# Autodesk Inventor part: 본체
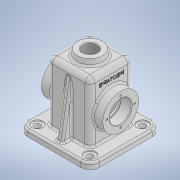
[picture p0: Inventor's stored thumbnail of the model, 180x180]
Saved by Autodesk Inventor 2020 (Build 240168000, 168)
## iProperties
Created: 2021-07
Part Number: 본체
Material: 일반
Document SubType Name: Modeling
Designer: Owner
Density: 1 g/cm^3
Appearance: 기본값
Author: Owner
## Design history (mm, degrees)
sketch "스케치1"
  geometry: L1 (34, 34)-(-34, 34); L2 (-34, 34)-(-34, -34); L3 (-34, -34)-(34, -34); L4 (34, -34)-(34, 34); L5 (34, 34)-(-34, -34); L6 (-34, 34)-(34, -34); 1 further point
  constraints: 12 end point, 2 midpoint, 2 parallel, 1 horizontal, 1 perpendicular
  dimensions: "d0" = 68 distance of L3.end L2.end; "d1" = 68 distance of L2.end L1.end
extrude "돌출1" new body sketch "스케치1" distance "d2" = 105; taper "d3" = 0 deg
fillet "모깎기1" dims "d4" = 8
feature "쉘1" dims "d5" = 5
sketch "스케치2"
  geometry: L1 (-57, 57)-(57, 57); L2 (57, 57)-(57, -57); L3 (57, -57)-(-57, -57); L4 (-57, -57)-(-57, 57); L5 (-57, 57)-(57, -57); L6 (57, 57)-(-57, -57); L7 (-26, 29)-(26, 29) reference; L8 (29, 26)-(29, -26) reference; L9 (26, -29)-(-26, -29) reference; L10 (-29, -26)-(-29, 26) reference; L11 (34, 26)-(34, -26) reference; L12 (-26, 34)-(26, 34) reference; L13 (-34, -26)-(-34, 26) reference; L14 (26, -34)-(-26, -34) reference; A1 r 3 centre (-26, 26) between (-26, 29) and (-29, 26) reference; A2 r 3 centre (26, 26) between (29, 26) and (26, 29) reference; A3 r 3 centre (26, -26) between (26, -29) and (29, -26) reference; A4 r 3 centre (-26, -26) between (-29, -26) and (-26, -29) reference; A5 r 8 centre (26, -26) between (26, -34) and (34, -26) reference; A6 r 8 centre (26, 26) between (34, 26) and (26, 34) reference; A7 r 8 centre (-26, 26) between (-26, 34) and (-34, 26) reference; A8 r 8 centre (-26, -26) between (-34, -26) and (-26, -34) reference; 1 further point
  constraints: 12 end point, 2 midpoint, 2 parallel, 1 horizontal, 1 perpendicular
  dimensions: "d6" = 114 distance of L2.end L3.end; "d7" = 114 distance of L1.end L2.end
extrude "돌출2" join sketch "스케치2" distance "d8" = 10; taper "d9" = 0 deg
fillet "모깎기2" dims "d10" = 15
fillet "모깎기3" dims "d11" = 3
node "작업 평면1"
sketch "스케치3"
  geometry: L1 (68, -97)-(-16, -97) reference; C1 r 28.5 at (26, -45); 2 further points
  constraints: 1 centre point, 1 midpoint, 1 vertical alignment
  dimensions: "d13" = 52 distance from line of L1 C1.centre; "d14" = 57 diameter of C1
extrude "돌출4" join sketch "스케치3" stored distance "d17" = 10; taper "d18" = 0 deg
fillet "모깎기4" dims "d19" = 3
sketch "스케치4"
  geometry: C1 r 28.5 at (0, 0) reference; C2 r 17.5 at (0, 0); 1 further point
  constraints: 1 centre point, 1 coincident
  dimensions: "d20" = 35 diameter of C2
extrude "돌출5" cut sketch "스케치4" distance "d21" = 17; taper "d22" = 0 deg
sketch "스케치5"
  geometry: C1 r 17.5 at (0, 0) reference; C2 r 15 at (0, 0)
  constraints: 1 centre point, 1 coincident
  dimensions: "d23" = 30 diameter of C2
extrude "돌출6" cut sketch "스케치5" distance "d24" = 3; taper "d25" = 0 deg
node "작업 평면2"
node "작업 평면3"
node "작업 평면4"
node "작업 평면5"
sketch "스케치6"
  geometry: L1 (68, -97)-(-16, -97) reference; C1 r 28.5 at (26, -45); 2 further points
  constraints: 1 centre point, 1 midpoint, 1 vertical alignment
  dimensions: "d28" = 52 distance from line of L1 C1.centre; "d29" = 57 diameter of C1
extrude "돌출7" join sketch "스케치6" stored distance "d30" = 3; taper "d31" = 0 deg
sketch "스케치7"
  geometry: C1 r 28.5 at (0, 0) reference; C2 r 17.5 at (0, 0) reference; C3 r 17.5 at (0, 0); 1 further point
  constraints: 1 centre point, 1 coincident
  dimensions: "d32" = 35 diameter of C3
extrude "돌출8" cut sketch "스케치7" distance "d33" = 17; taper "d34" = 0 deg
sketch "스케치8"
  geometry: C1 r 17.5 at (0, 0) reference; C2 r 28.5 at (0, 0) reference; C3 r 17.5 at (0, 0) reference; C4 r 15 at (0, 0); 1 further point
  constraints: 1 centre point, 1 coincident
  dimensions: "d35" = 30 diameter of C4
extrude "돌출9" cut sketch "스케치8" distance "d36" = 3; taper "d37" = 0 deg
fillet "모깎기5" dims "d38" = 3
sketch "스케치9"
  geometry: C1 r 28.5 at (0, 0) reference; 2 further points
  constraints: 1 vertical alignment
  dimensions: "d39" = 22 distance of C1.centre point (0, 22)
hole "구멍1" sketch "스케치9" at (0, 22) diameter "d40" = 3.242; stored, may be unused: countersink angle "d44" = 90 deg, drill point angle "d46" = 118 deg; dims "d41" = 8, "d42" = 4, "d43" = 2, "d45" = 10
node "작업 평면6"
sketch "스케치10"
  geometry: C1 r 20 at (0, 0); 1 further point
  constraints: 1 centre point, 1 coincident
  dimensions: "d51" = 40 diameter of C1
extrude "돌출10" join sketch "스케치10" stored distance "d52" = 3; taper "d53" = 8 deg
sketch "스케치11"
  geometry: C1 r 20 at (0, 0) reference; 2 further points
  constraints: 1 coincident
hole "구멍2" sketch "스케치11" at (0, 0) diameter "d54" = 22.83494; stored, may be unused: countersink angle "d58" = 90 deg, drill point angle "d60" = 0 deg; dims "d55" = 50, "d56" = 4, "d57" = 2, "d59" = 59.3
chamfer "모따기1" distance "d61" = 1; stored, may be unused: second distance "d62" = 2, angle "d63" = 45 deg
fillet "모깎기6" dims "d64" = 3
sketch "스케치12"
  geometry: L1 (46, 18)-(6, 18) reference; 3 further points
  constraints: 1 midpoint, 1 vertical alignment, 1 other
  dimensions: "d65" = 25 distance from line of point (26, -7) L1
feature "엠보싱1" sketch "스케치12" dims "d66" = 0.5, "d67" = 0
fillet "모깎기7" dims "d68" = 0.3
sketch "스케치13"
  geometry: L1 (37.966, -44.069)-(10, -49); L2 (0, -57)-(7, -57) reference; L3 (10, -42)-(10, -54) reference; 1 further point
  constraints: 2 end point, 1 point on line
  dimensions: "d69" = 8 distance from line of L2 L1.end; "d73" = 10 deg angle of L2 L1
feature "리브1" sketch "스케치13" dims "d74" = 1, "d75" = 10, "d76" = 0, "d77" = 0, "d78" = 1, "d79" = 1
fillet "모깎기8" dims "d80" = 3
fillet "모깎기9" dims "d81" = 3
sketch "스케치14"
  geometry: A1 r 15 centre (-42, -42) between (-57, -42) and (-42, -57) reference; 2 further points
  constraints: 1 coincident
hole "구멍3" sketch "스케치14" at (-42, -42) diameter "d82" = 10; stored, may be unused: countersink angle "d86" = 90 deg, drill point angle "d88" = 0 deg; dims "d83" = 50, "d84" = 18, "d85" = 2, "d87" = 10
node "솔리드1"
pattern_circular "원형 패턴1" dims angle "d48" = 360 deg
mirror "미러1"
mirror "미러2"
mirror "미러3"
mirror "미러4"
node "투영된 루프1"
node "투영된 루프2"
feature "A9D066F2-1C7D-4E18-AEED-F7BC21143FA4" dims "d82" = 10, "d83" = 50, "d84" = 18, "d85" = 2, "d86" = 90 deg, "d87" = 10, "d88" = 0
other parameters: "d12" = 15, "d26" = 15, "d27" = 15, "d50" = 115
